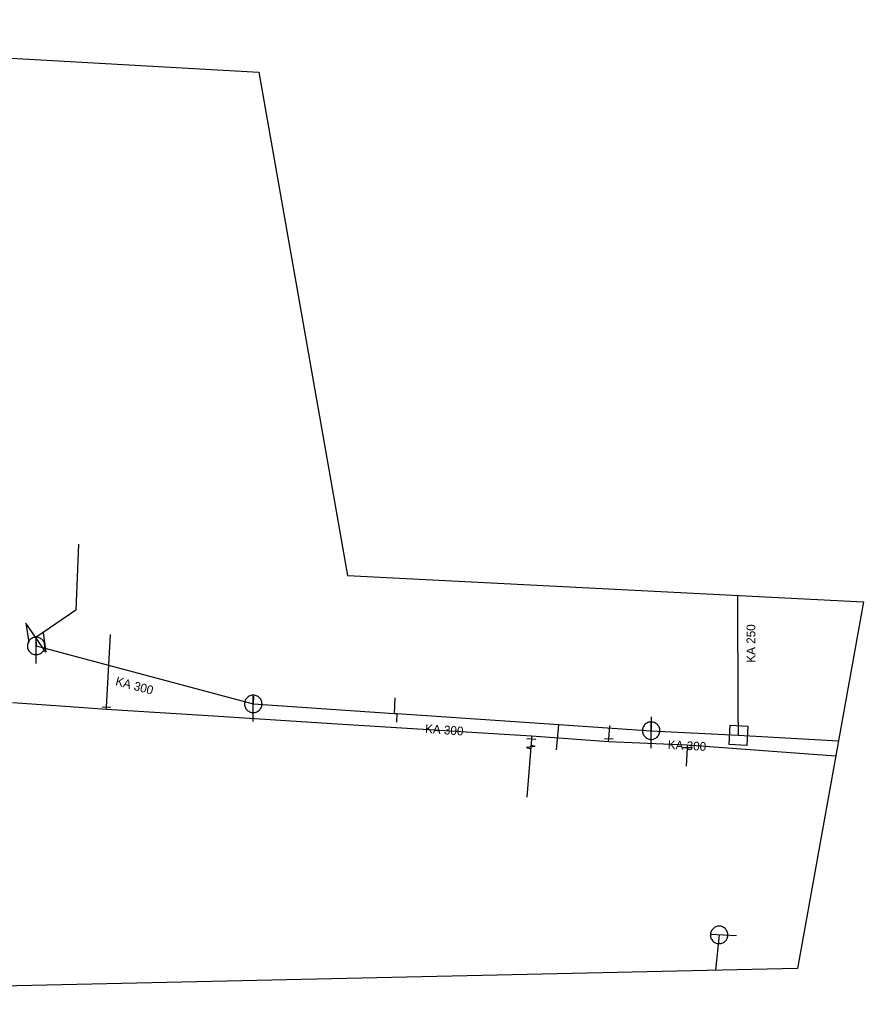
# Model space of a CAD drawing. Extents: x -716525 to -716349, y -954127 to -954015.
# Drawn here: x -716445.8 to -716349.3, y -954126.6 to -954014.6 of the extents above; entities that cross this region are included whole.
import ezdxf

# ---------------------------------------------------------------- set-up
doc = ezdxf.new("R2010")
doc.units = 0
for name, color, linetype in [('Vrstva 1', 7, 'Continuous'), ('Vrstva 11', 7, 'Continuous'), ('Vrstva 13', 7, 'Continuous'), ('Vrstva 14', 7, 'Continuous'), ('Vrstva 17', 7, 'Continuous'), ('Vrstva 22', 7, 'Continuous'), ('Vrstva 31', 7, 'Continuous'), ('Vrstva 34', 7, 'Continuous'), ('Vrstva 47', 7, 'Continuous'), ('Vrstva 63', 7, 'Continuous')]:
    doc.layers.add(name, color=color, linetype=linetype)

msp = doc.modelspace()

# ---------------------------------------------------------------- linework, layer by layer
at = {"layer": 'Vrstva 11'}
for points in [[(-716439.067, -954074.563), (-716439.381, -954082.11), (-716443.93, -954085.26)], [(-716443.93, -954085.26), (-716443.91, -954086.21)], [(-716419.059, -954091.96), (-716419.079, -954092.829)], [(-716402.89, -954092.151), (-716402.96, -954093.92)], [(-716402.655, -954094.91), (-716402.629, -954093.949)], [(-716384.406, -954098.096), (-716384.16, -954095.19)], [(-716373.603, -954094.329), (-716373.59, -954095.899)]]:
    msp.add_lwpolyline(points, dxfattribs=at)
at = {"layer": 'Vrstva 13'}
for points in [[(-716435.87, -954093.191), (-716435.42, -954084.91)], [(-716378.438, -954096.813), (-716378.307, -954095.293)], [(-716387.287, -954096.86), (-716387.35, -954097.77)], [(-716387.35, -954097.77), (-716387.806, -954103.495)], [(-716369.475, -954097.855), (-716369.598, -954099.953)]]:
    msp.add_lwpolyline(points, dxfattribs=at)
at = {"layer": 'Vrstva 14'}
for points in [[(-716363.708, -954080.434), (-716363.667, -954093.467), (-716363.632, -954096.419)], [(-716443.91, -954086.21), (-716419.079, -954092.829)], [(-716435.876, -954093.455), (-716435.87, -954093.191)], [(-716419.079, -954092.829), (-716402.96, -954093.92), (-716402.629, -954093.949), (-716384.16, -954095.19), (-716373.59, -954095.899)], [(-716387.266, -954096.485), (-716387.287, -954096.86)], [(-716373.59, -954095.899), (-716363.632, -954096.419)], [(-716363.632, -954096.419), (-716352.184, -954097.041)], [(-716378.456, -954097.125), (-716378.438, -954096.813)], [(-716369.476, -954097.505), (-716369.475, -954097.855)], [(-716365.82, -954119.252), (-716366.248, -954123.292)]]:
    msp.add_lwpolyline(points, dxfattribs=at)
at = {"layer": 'Vrstva 17'}
msp.add_lwpolyline([(-716446.614, -954092.66), (-716441.116, -954093.066), (-716435.876, -954093.455), (-716424.218, -954094.18), (-716409.455, -954095.1), (-716395.355, -954095.978), (-716387.266, -954096.485), (-716378.456, -954097.125), (-716369.476, -954097.505), (-716352.497, -954098.776)], dxfattribs=at)
at = {"layer": 'Vrstva 22'}
for points in [[(-716442.91, -954086.21), (-716442.915, -954086.101), (-716442.933, -954085.993), (-716442.963, -954085.887), (-716443.003, -954085.786), (-716443.055, -954085.689), (-716443.117, -954085.599), (-716443.189, -954085.516), (-716443.269, -954085.442), (-716443.357, -954085.376), (-716443.451, -954085.321), (-716443.551, -954085.276), (-716443.656, -954085.243), (-716443.763, -954085.221), (-716443.872, -954085.211), (-716443.982, -954085.213), (-716444.09, -954085.227), (-716444.197, -954085.252), (-716444.3, -954085.289), (-716444.398, -954085.338), (-716444.49, -954085.396), (-716444.576, -954085.465), (-716444.653, -954085.542), (-716444.722, -954085.628), (-716444.781, -954085.72), (-716444.829, -954085.818), (-716444.866, -954085.921), (-716444.892, -954086.028), (-716444.906, -954086.136), (-716444.909, -954086.246), (-716444.899, -954086.355), (-716444.878, -954086.462), (-716444.844, -954086.566), (-716444.8, -954086.666), (-716444.745, -954086.761), (-716444.679, -954086.849), (-716444.605, -954086.929), (-716444.522, -954087.001), (-716444.432, -954087.063), (-716444.336, -954087.115), (-716444.234, -954087.156), (-716444.129, -954087.186), (-716444.021, -954087.204), (-716443.911, -954087.21), (-716443.802, -954087.204), (-716443.694, -954087.186), (-716443.589, -954087.157), (-716443.487, -954087.116), (-716443.39, -954087.064), (-716443.3, -954087.002), (-716443.217, -954086.931), (-716443.142, -954086.851), (-716443.077, -954086.763), (-716443.021, -954086.669), (-716442.977, -954086.569), (-716442.943, -954086.465), (-716442.921, -954086.357), (-716442.911, -954086.248), (-716442.91, -954086.21)], [(-716443.91, -954088.21), (-716443.909, -954085.21)], [(-716418.079, -954092.829), (-716418.084, -954092.72), (-716418.102, -954092.612), (-716418.132, -954092.506), (-716418.172, -954092.405), (-716418.224, -954092.308), (-716418.286, -954092.218), (-716418.358, -954092.135), (-716418.438, -954092.061), (-716418.526, -954091.995), (-716418.62, -954091.94), (-716418.72, -954091.895), (-716418.825, -954091.862), (-716418.932, -954091.84), (-716419.041, -954091.83), (-716419.151, -954091.832), (-716419.259, -954091.846), (-716419.366, -954091.871), (-716419.469, -954091.908), (-716419.567, -954091.957), (-716419.659, -954092.015), (-716419.745, -954092.084), (-716419.822, -954092.161), (-716419.891, -954092.247), (-716419.95, -954092.339), (-716419.998, -954092.437), (-716420.035, -954092.54), (-716420.061, -954092.647), (-716420.075, -954092.755), (-716420.078, -954092.865), (-716420.068, -954092.974), (-716420.047, -954093.081), (-716420.013, -954093.185), (-716419.969, -954093.285), (-716419.914, -954093.38), (-716419.848, -954093.468), (-716419.774, -954093.548), (-716419.691, -954093.62), (-716419.601, -954093.682), (-716419.505, -954093.734), (-716419.403, -954093.775), (-716419.298, -954093.805), (-716419.19, -954093.823), (-716419.08, -954093.829), (-716418.971, -954093.823), (-716418.863, -954093.805), (-716418.758, -954093.776), (-716418.656, -954093.735), (-716418.559, -954093.683), (-716418.469, -954093.621), (-716418.386, -954093.55), (-716418.311, -954093.47), (-716418.246, -954093.382), (-716418.19, -954093.288), (-716418.146, -954093.188), (-716418.112, -954093.084), (-716418.09, -954092.976), (-716418.08, -954092.867), (-716418.079, -954092.829)], [(-716419.079, -954094.829), (-716419.078, -954091.829)], [(-716372.59, -954095.899), (-716372.595, -954095.79), (-716372.613, -954095.682), (-716372.643, -954095.576), (-716372.683, -954095.475), (-716372.735, -954095.378), (-716372.797, -954095.288), (-716372.869, -954095.205), (-716372.949, -954095.131), (-716373.037, -954095.065), (-716373.131, -954095.01), (-716373.231, -954094.965), (-716373.336, -954094.932), (-716373.443, -954094.91), (-716373.552, -954094.9), (-716373.662, -954094.902), (-716373.77, -954094.916), (-716373.877, -954094.941), (-716373.98, -954094.978), (-716374.078, -954095.027), (-716374.17, -954095.085), (-716374.256, -954095.154), (-716374.333, -954095.231), (-716374.402, -954095.317), (-716374.461, -954095.409), (-716374.509, -954095.507), (-716374.546, -954095.61), (-716374.572, -954095.717), (-716374.586, -954095.825), (-716374.589, -954095.935), (-716374.579, -954096.044), (-716374.558, -954096.151), (-716374.524, -954096.255), (-716374.48, -954096.355), (-716374.425, -954096.45), (-716374.359, -954096.538), (-716374.285, -954096.618), (-716374.202, -954096.69), (-716374.112, -954096.752), (-716374.016, -954096.804), (-716373.914, -954096.845), (-716373.809, -954096.875), (-716373.701, -954096.893), (-716373.591, -954096.899), (-716373.482, -954096.893), (-716373.374, -954096.875), (-716373.269, -954096.846), (-716373.167, -954096.805), (-716373.07, -954096.753), (-716372.98, -954096.691), (-716372.897, -954096.62), (-716372.822, -954096.54), (-716372.757, -954096.452), (-716372.701, -954096.358), (-716372.657, -954096.258), (-716372.623, -954096.154), (-716372.601, -954096.046), (-716372.591, -954095.937), (-716372.59, -954095.899)], [(-716373.59, -954097.899), (-716373.589, -954094.899)], [(-716364.551, -954095.277), (-716362.521, -954095.388), (-716362.64, -954097.578), (-716364.67, -954097.467), (-716364.551, -954095.277)], [(-716365.773, -954118.253), (-716365.882, -954118.254), (-716365.991, -954118.267), (-716366.098, -954118.292), (-716366.201, -954118.327), (-716366.3, -954118.374), (-716366.393, -954118.432), (-716366.479, -954118.5), (-716366.557, -954118.577), (-716366.627, -954118.662), (-716366.686, -954118.753), (-716366.736, -954118.851), (-716366.773, -954118.954), (-716366.8, -954119.06), (-716366.815, -954119.169), (-716366.818, -954119.279), (-716366.809, -954119.387), (-716366.789, -954119.495), (-716366.757, -954119.6), (-716366.713, -954119.7), (-716366.659, -954119.794), (-716366.594, -954119.884), (-716366.521, -954119.964), (-716366.438, -954120.037), (-716366.349, -954120.1), (-716366.253, -954120.153), (-716366.152, -954120.194), (-716366.046, -954120.225), (-716365.939, -954120.244), (-716365.829, -954120.251), (-716365.72, -954120.246), (-716365.612, -954120.23), (-716365.506, -954120.201), (-716365.404, -954120.162), (-716365.307, -954120.111), (-716365.216, -954120.049), (-716365.133, -954119.979), (-716365.057, -954119.899), (-716364.991, -954119.812), (-716364.935, -954119.719), (-716364.889, -954119.619), (-716364.854, -954119.515), (-716364.831, -954119.408), (-716364.82, -954119.299), (-716364.821, -954119.189), (-716364.834, -954119.081), (-716364.858, -954118.974), (-716364.895, -954118.871), (-716364.942, -954118.771), (-716365, -954118.679), (-716365.067, -954118.592), (-716365.143, -954118.514), (-716365.228, -954118.445), (-716365.32, -954118.385), (-716365.417, -954118.336), (-716365.52, -954118.297), (-716365.627, -954118.27), (-716365.735, -954118.255), (-716365.773, -954118.253)], [(-716363.821, -954119.344), (-716366.818, -954119.206)]]:
    msp.add_lwpolyline(points, dxfattribs=at)
at = {"layer": 'Vrstva 31'}
for points in [[(-716442.791, -954086.903), (-716445.068, -954083.615)], [(-716445.068, -954083.615), (-716444.752, -954085.828)], [(-716443.108, -954084.69), (-716442.791, -954086.903)]]:
    msp.add_lwpolyline(points, dxfattribs=at)
at = {"layer": 'Vrstva 34'}
for points in [[(-716436.369, -954093.18), (-716435.37, -954093.202)], [(-716386.788, -954096.894), (-716387.785, -954096.824)], [(-716378.937, -954096.785), (-716377.938, -954096.841)], [(-716368.975, -954097.852), (-716369.974, -954097.856)]]:
    msp.add_lwpolyline(points, dxfattribs=at)
at = {"layer": 'Vrstva 47'}
for points in [[(-716386.844, -954097.706), (-716387.336, -954097.569)], [(-716386.844, -954097.706), (-716387.855, -954097.833)], [(-716387.855, -954097.833), (-716387.363, -954097.97)]]:
    msp.add_lwpolyline(points, dxfattribs=at)
at = {"layer": 'Vrstva 63'}
msp.add_lwpolyline([(-716525.013, -954014.583), (-716418.454, -954020.591), (-716418.452, -954020.591), (-716418.45, -954020.592), (-716418.448, -954020.593), (-716418.447, -954020.594), (-716418.446, -954020.596), (-716418.445, -954020.597), (-716418.444, -954020.599), (-716408.311, -954078.151), (-716349.335, -954081.17), (-716349.333, -954081.17), (-716349.331, -954081.171), (-716349.33, -954081.172), (-716349.328, -954081.173), (-716349.327, -954081.174), (-716349.326, -954081.176), (-716349.326, -954081.178), (-716349.325, -954081.18), (-716349.326, -954081.182), (-716356.876, -954123.076), (-716356.877, -954123.078), (-716356.877, -954123.08), (-716356.879, -954123.081), (-716356.88, -954123.083), (-716356.882, -954123.084), (-716356.884, -954123.084), (-716356.886, -954123.084), (-716516.511, -954126.626)], dxfattribs=at)

# ---------------------------------------------------------------- texts
at = {"layer": 'Vrstva 1'}
for s, rotation, p in [('KA 250', 90, (-716361.682, -954088.117)), ('KA 300', 345, (-716434.904, -954090.665)), ('KA 300', 356, (-716399.461, -954096.152)), ('KA 300', 357, (-716371.709, -954097.985))]:
    msp.add_text(s, height=1, rotation=rotation, dxfattribs=at).set_placement(p)

doc.saveas('drawing.dxf')
